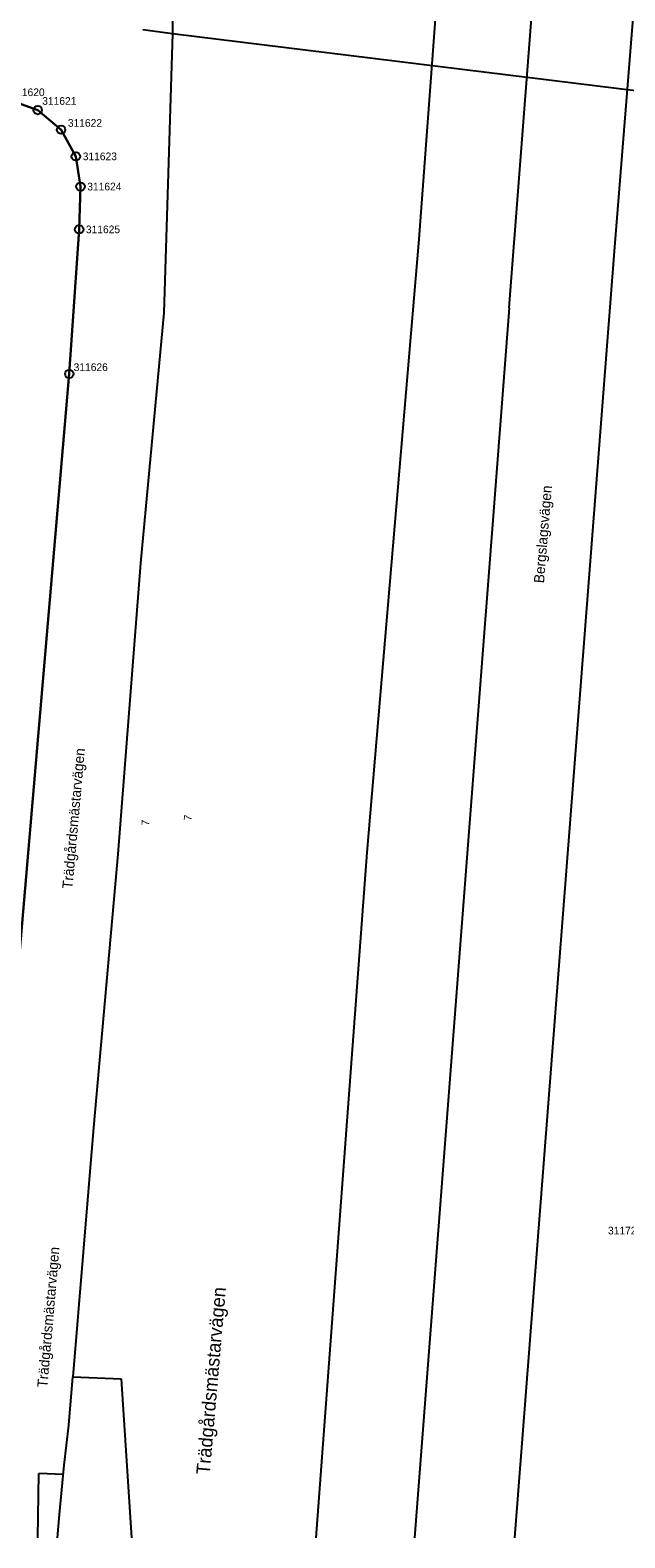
# Model space of a CAD drawing. Extents: x 141995 to 152570, y 6580184 to 6586000.
# Drawn here: x 142372.2 to 142442.1, y 6585000 to 6585177.1 of the extents above; entities that cross this region are included whole.
import ezdxf

# ---------------------------------------------------------------- set-up
doc = ezdxf.new("R2010")
doc.units = 0
for name, color, linetype in [('Level 10', 7, 'Continuous'), ('Level 13', 7, 'Continuous'), ('Level 20', 7, 'Continuous'), ('Level 21', 7, 'Continuous'), ('Level 40', 7, 'Continuous'), ('Level 42', 7, 'Continuous'), ('Level 43', 7, 'Continuous'), ('Level 5', 7, 'Continuous'), ('Level 53', 7, 'Continuous'), ('Level 54', 7, 'Continuous'), ('Level 55', 7, 'Continuous'), ('Level 6', 7, 'Continuous'), ('Level 7', 7, 'Continuous'), ('Level 8', 7, 'Continuous')]:
    doc.layers.add(name, color=color, linetype=linetype)

msp = doc.modelspace()

# ---------------------------------------------------------------- linework, layer by layer
at = {"layer": 'Level 10'}
for centre in [(142373.13, 6585167.75), (142375.87, 6585165.44), (142377.61, 6585162.31), (142378.15, 6585158.76), (142377.99, 6585153.73), (142376.84, 6585136.75)]:
    msp.add_circle(centre, 0.5, dxfattribs=at)
at = {"layer": 'Level 13'}
for points in [[(142456.17, 6585342.76), (142440.83, 6585151.19)], [(142431.86, 6585340.99), (142417.9, 6585152.6)], [(142388.96, 6585188), (142388.97, 6585176.76)], [(142388.97, 6585176.76), (142387.96, 6585143.93), (142385.2, 6585114.53), (142382.54, 6585080.31), (142379.67, 6585048.23), (142377.26, 6585018.93)], [(142417.9, 6585152.6), (142411.77, 6585080.51), (142405.8, 6585000)], [(142440.83, 6585151.19), (142429.14, 6585000)], [(142373.13, 6585000), (142373.27, 6585007.57)], [(142376.17, 6585007.44), (142373.27, 6585007.57)]]:
    msp.add_lwpolyline(points, dxfattribs=at)
at = {"layer": 'Level 20'}
for points in [[(142428.51, 6585144.51), (142436.21, 6585244.62)], [(142428.51, 6585144.51), (142417.37, 6585000)]]:
    msp.add_lwpolyline(points, dxfattribs=at)
at = {"layer": 'Level 21'}
for points in [[(142428.51, 6585144.51), (142436.21, 6585244.62)], [(142428.51, 6585144.51), (142417.37, 6585000)]]:
    msp.add_lwpolyline(points, dxfattribs=at)
at = {"layer": 'Level 5'}
for points in [[(142369.76, 6585168.94), (142373.13, 6585167.75)], [(142373.13, 6585167.75), (142375.87, 6585165.44)], [(142375.87, 6585165.44), (142377.61, 6585162.31)], [(142377.61, 6585162.31), (142378.15, 6585158.76)], [(142378.15, 6585158.76), (142377.99, 6585153.73)], [(142377.99, 6585153.73), (142376.84, 6585136.75)], [(142376.84, 6585136.75), (142367.36, 6585026.44)]]:
    msp.add_lwpolyline(points, dxfattribs=at)
at = {"layer": 'Level 6'}
msp.add_lwpolyline([(142228.18, 6585027.1), (142249.62, 6585025.47), (142274.29, 6585023.58), (142278.9, 6585023.24), (142304.43, 6585021.29), (142325.88, 6585019.66), (142352.75, 6585017.61), (142356.64, 6585017.32), (142360.49, 6585017.78), (142363.88, 6585019.67), (142366.29, 6585022.71), (142367.36, 6585026.44), (142376.84, 6585136.75), (142377.99, 6585153.73), (142378.15, 6585158.76), (142377.61, 6585162.31), (142375.87, 6585165.44), (142373.13, 6585167.75), (142369.76, 6585168.94), (142367.8, 6585169.26), (142344.13, 6585173.11), (142322.83, 6585176.58), (142298, 6585180.62)], dxfattribs=at)
at = {"layer": 'Level 7'}
for points in [[(142376.78, 6585013.22), (142377.26, 6585018.93)], [(142377.26, 6585018.93), (142382.92, 6585018.7)], [(142382.92, 6585018.7), (142384.16, 6585000)], [(142376.25, 6585008.52), (142376.78, 6585013.22)], [(142375.69, 6585002.74), (142376.25, 6585008.52)], [(142375.44, 6585000), (142375.69, 6585002.74)]]:
    msp.add_lwpolyline(points, dxfattribs=at)
at = {"layer": 'Level 8'}
for points in [[(142385.46, 6585177.2), (142388.97, 6585176.76)], [(142388.97, 6585176.76), (142457.02, 6585168.35)]]:
    msp.add_lwpolyline(points, dxfattribs=at)

# ---------------------------------------------------------------- texts
at = {"layer": 'Level 40'}
for s, rotation, p in [('Bergslagsvägen', 85.3118, (142432.59, 6585112.13)), ('Trädgårdsmästarvägen', 85.0258, (142374.26, 6585017.61))]:
    msp.add_text(s, height=1.2, rotation=rotation, dxfattribs=at).set_placement(p)
at = {"layer": 'Level 42'}
msp.add_text('Trädgårdsmästarvägen', height=1.2, rotation=84.8558, dxfattribs=at).set_placement((142377.2, 6585076.2))
at = {"layer": 'Level 43'}
msp.add_text('Trädgårdsmästarvägen', height=1.6, rotation=85.0258, dxfattribs=at).set_placement((142393.33, 6585007.36))
at = {"layer": 'Level 53'}
for s, p in [('311620', (142369.93, 6585169.39)), ('311621', (142373.66, 6585168.37)), ('311622', (142376.67, 6585165.79)), ('311623', (142378.42, 6585161.86)), ('311624', (142378.95, 6585158.31)), ('311625', (142378.79, 6585153.28)), ('311626', (142377.35, 6585137.09)), ('311722', (142440.11, 6585035.65))]:
    msp.add_text(s, height=0.9, rotation=0.0522, dxfattribs=at).set_placement(p)
at = {"layer": 'Level 54'}
msp.add_text('7', height=0.9, rotation=83.0418, dxfattribs=at).set_placement((142391.17, 6585084.23))
at = {"layer": 'Level 55'}
msp.add_text('7', height=0.9, rotation=85.5418, dxfattribs=at).set_placement((142386.21, 6585083.65))

doc.saveas('drawing.dxf')
